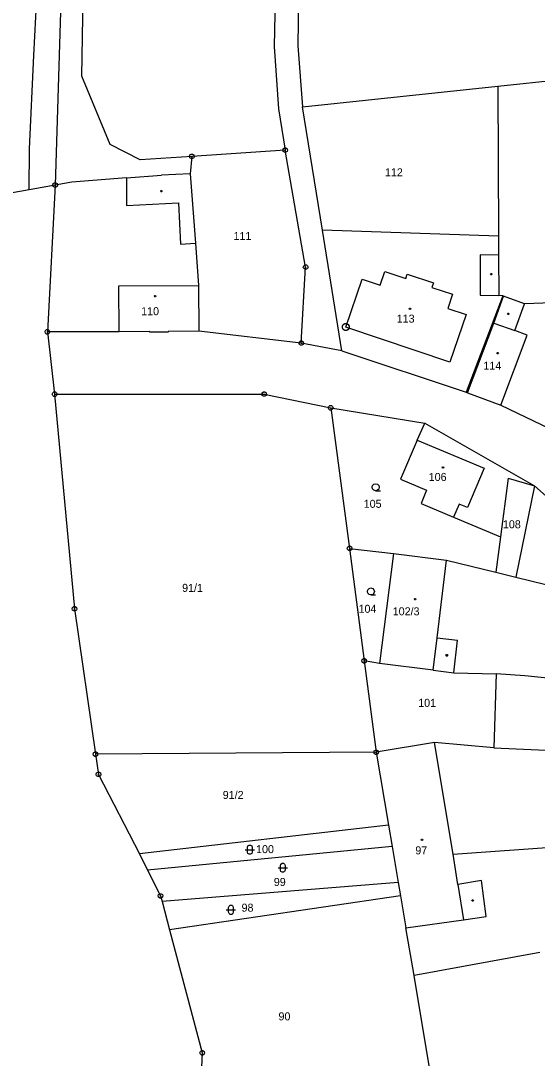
# Model space of a CAD drawing. Extents: x -812394 to -807601, y -1013098 to -1009266.
# Drawn here: x -809886.4 to -809776.7, y -1010813 to -1010592.7 of the extents above; entities that cross this region are included whole.
import ezdxf

# ---------------------------------------------------------------- set-up
doc = ezdxf.new("R2010")
doc.units = 0
for name, color, linetype in [('KN_HRANICE', 7, 'Continuous'), ('KN_KULTURY', 7, 'Continuous'), ('KN_MEZNIKY', 7, 'Continuous'), ('KN_PARCELY', 7, 'Continuous'), ('KN_SLUCKY', 7, 'Continuous'), ('KN_VEDENI', 7, 'Continuous')]:
    doc.layers.add(name, color=color, linetype=linetype)

# ---------------------------------------------------------------- blocks, each defined once
blk = doc.blocks.new('101')
blk.add_line((-0.05, 0), (0.05, 0))
blk.add_lwpolyline([(0.19, 0.72), (0.53, 0.53), (0.72, 0.19), (0.72, -0.2), (0.53, -0.54), (0.19, -0.73), (-0.2, -0.73), (-0.54, -0.54), (-0.73, -0.2), (-0.73, 0.19), (-0.54, 0.53), (-0.2, 0.72), (0.19, 0.72)])
blk = doc.blocks.new('304')
blk.add_lwpolyline([(0, 0), (-0.38, 0.1), (-0.65, 0.37), (-0.75, 0.74), (-0.65, 1.11), (-0.38, 1.38), (-0.01, 1.48), (0.36, 1.38), (0.63, 1.11), (0.73, 0.73), (0.63, 0.35), (0.36, 0.08), (-0.02, -0.02), (0.98, -0.02)])
blk = doc.blocks.new('316')
for points in [[(-1, 1), (0.27, 1), (1, 1)], [(-0.5, 1.5), (-0.4, 1.79), (-0.15, 1.97), (0.16, 1.97), (0.41, 1.79), (0.51, 1.5), (0.51, 0.5), (0.41, 0.21), (0.16, 0.03), (-0.15, 0.03), (-0.4, 0.21), (-0.5, 0.5), (-0.5, 1.5)]]:
    blk.add_lwpolyline(points)
blk = doc.blocks.new('402')
blk.add_lwpolyline([(0.09, 0.15), (0.18, 0), (0.09, -0.15), (-0.09, -0.15), (-0.18, 0), (-0.09, 0.15), (0.09, 0.15)])
blk = doc.blocks.new('105')
blk.add_line((-0.12, 0), (0.12, 0))
blk.add_lwpolyline([(0.15, 0.48), (0.4, 0.3), (0.5, 0.01), (0.4, -0.28), (0.15, -0.46), (-0.16, -0.46), (-0.41, -0.28), (-0.51, 0.01), (-0.41, 0.3), (-0.16, 0.48), (0.15, 0.48)])

msp = doc.modelspace()

# ---------------------------------------------------------------- linework, layer by layer
at = {"layer": 'KN_HRANICE'}
for p, q in [((-809873.36, -1010604.47), (-809872.78, -1010570.15)), ((-809832.23, -1010581.05), (-809832.51, -1010598.19)), ((-809827.23, -1010580.92), (-809827.51, -1010598.06)), ((-809877.92, -1010590.8), (-809879.03, -1010627.62)), ((-809832.51, -1010598.19), (-809831.62, -1010611.42)), ((-809827.51, -1010598.06), (-809826.5, -1010610.99)), ((-809785.03, -1010606.6), (-809746.74, -1010602.54)), ((-809867.35, -1010619), (-809873.36, -1010604.47)), ((-809826.5, -1010610.99), (-809785.03, -1010606.6)), ((-809785.03, -1010606.6), (-809784.91, -1010638.49)), ((-809831.62, -1010611.42), (-809830.2, -1010620.19)), ((-809822.29, -1010637.21), (-809826.5, -1010610.99)), ((-809860.96, -1010622.27), (-809867.35, -1010619)), ((-809830.2, -1010620.19), (-809850.01, -1010621.53)), ((-809825.85, -1010645.04), (-809830.2, -1010620.19)), ((-809850.01, -1010621.53), (-809860.96, -1010622.27)), ((-809850.01, -1010621.53), (-809850.38, -1010625.24)), ((-809850.38, -1010625.24), (-809856.43, -1010625.49)), ((-809850.38, -1010625.24), (-809849.27, -1010639.96)), ((-809879.03, -1010627.62), (-809884.55, -1010628.63)), ((-809879.03, -1010627.62), (-809880.69, -1010658.8)), ((-809875.47, -1010626.99), (-809879.03, -1010627.62)), ((-809863.92, -1010626.08), (-809875.47, -1010626.99)), ((-809863.92, -1010626.08), (-809856.43, -1010625.49)), ((-809884.55, -1010628.63), (-809898.33, -1010631.14)), ((-809784.91, -1010638.49), (-809822.29, -1010637.21)), ((-809818.18, -1010662.82), (-809822.29, -1010637.21)), ((-809784.91, -1010638.49), (-809784.89, -1010642.49)), ((-809849.27, -1010639.96), (-809848.59, -1010648.97)), ((-809784.89, -1010642.49), (-809784.86, -1010651.09)), ((-809826.78, -1010661.18), (-809825.85, -1010645.04)), ((-809848.59, -1010648.97), (-809848.53, -1010658.67)), ((-809784.01, -1010651.14), (-809791.73, -1010671.61)), ((-809784.01, -1010651.14), (-809784.86, -1010651.09)), ((-809783.82, -1010651.21), (-809784.01, -1010651.14)), ((-809779.36, -1010652.87), (-809783.82, -1010651.21)), ((-809773.49, -1010652.65), (-809779.36, -1010652.87)), ((-809865.45, -1010658.79), (-809880.69, -1010658.8)), ((-809880.69, -1010658.8), (-809879.15, -1010672.04)), ((-809858.96, -1010658.74), (-809865.45, -1010658.79)), ((-809858.96, -1010658.89), (-809858.96, -1010658.74)), ((-809855.08, -1010658.87), (-809858.96, -1010658.89)), ((-809848.53, -1010658.67), (-809855.08, -1010658.72)), ((-809855.08, -1010658.72), (-809855.08, -1010658.87)), ((-809826.78, -1010661.18), (-809848.53, -1010658.67)), ((-809818.18, -1010662.82), (-809826.78, -1010661.18)), ((-809818.18, -1010662.82), (-809791.73, -1010671.61)), ((-809791.73, -1010671.61), (-809791.45, -1010671.71)), ((-809791.45, -1010671.71), (-809784.4, -1010674.33)), ((-809879.15, -1010672.04), (-809834.64, -1010672.02)), ((-809879.15, -1010672.04), (-809874.93, -1010717.6)), ((-809834.64, -1010672.02), (-809820.53, -1010674.93)), ((-809820.53, -1010674.93), (-809816.51, -1010704.77)), ((-809820.53, -1010674.93), (-809800.51, -1010678.2)), ((-809784.4, -1010674.33), (-809774.04, -1010679.33)), ((-809802.14, -1010681.76), (-809800.51, -1010678.2)), ((-809800.51, -1010678.2), (-809777.22, -1010691.48)), ((-809802.14, -1010681.76), (-809805.72, -1010690.09)), ((-809805.72, -1010690.09), (-809800.16, -1010692.42)), ((-809782.82, -1010689.83), (-809784.46, -1010702.29)), ((-809782.82, -1010689.83), (-809777.22, -1010691.48)), ((-809777.22, -1010691.48), (-809781.21, -1010710.87)), ((-809777.22, -1010691.48), (-809766.01, -1010701.62)), ((-809800.16, -1010692.42), (-809801.34, -1010695.22)), ((-809801.34, -1010695.22), (-809794.45, -1010698.17)), ((-809794.45, -1010698.17), (-809784.46, -1010702.29)), ((-809784.46, -1010702.29), (-809785.46, -1010709.82)), ((-809816.51, -1010704.77), (-809813.43, -1010728.67)), ((-809816.51, -1010704.77), (-809807.17, -1010705.86)), ((-809807.17, -1010705.86), (-809810.15, -1010729.19)), ((-809807.17, -1010705.86), (-809795.91, -1010707.24)), ((-809797.91, -1010723.76), (-809795.91, -1010707.24)), ((-809795.91, -1010707.24), (-809785.46, -1010709.82)), ((-809785.46, -1010709.82), (-809781.21, -1010710.87)), ((-809781.21, -1010710.87), (-809771.66, -1010713.22)), ((-809874.93, -1010717.6), (-809870.46, -1010748.48)), ((-809798.74, -1010730.64), (-809797.91, -1010723.76)), ((-809813.43, -1010728.67), (-809810.87, -1010748.08)), ((-809810.15, -1010729.19), (-809813.43, -1010728.67)), ((-809798.74, -1010730.64), (-809810.15, -1010729.19)), ((-809798.74, -1010730.64), (-809794.37, -1010731.2)), ((-809794.37, -1010731.2), (-809785.42, -1010731.43)), ((-809785.42, -1010731.43), (-809785.91, -1010747.13)), ((-809779.32, -1010731.85), (-809785.42, -1010731.43)), ((-809752.63, -1010734.46), (-809779.32, -1010731.85)), ((-809798.52, -1010745.99), (-809810.87, -1010748.08)), ((-809785.91, -1010747.13), (-809798.52, -1010745.99)), ((-809794.5, -1010769.7), (-809798.52, -1010745.99)), ((-809810.87, -1010748.08), (-809870.46, -1010748.48)), ((-809870.46, -1010748.48), (-809869.85, -1010752.77)), ((-809810.87, -1010748.08), (-809808.24, -1010763.58)), ((-809785.91, -1010747.13), (-809765.89, -1010748.07)), ((-809869.85, -1010752.77), (-809861.14, -1010769.64)), ((-809808.24, -1010763.58), (-809861.14, -1010769.64)), ((-809808.24, -1010763.58), (-809807.48, -1010768.06)), ((-809807.48, -1010768.06), (-809859.41, -1010773.1)), ((-809807.48, -1010768.06), (-809806.19, -1010775.7)), ((-809794.5, -1010769.7), (-809750.96, -1010766.66)), ((-809861.14, -1010769.64), (-809859.41, -1010773.1)), ((-809793.54, -1010776.17), (-809794.5, -1010769.7)), ((-809859.41, -1010773.1), (-809856.66, -1010778.59)), ((-809806.19, -1010775.7), (-809856.35, -1010779.75)), ((-809806.19, -1010775.7), (-809805.71, -1010778.53)), ((-809788.53, -1010775.31), (-809793.54, -1010776.17)), ((-809787.51, -1010782.96), (-809788.53, -1010775.31)), ((-809856.66, -1010778.59), (-809856.35, -1010779.75)), ((-809805.71, -1010778.53), (-809854.75, -1010785.76)), ((-809805.71, -1010778.53), (-809804.56, -1010785.33)), ((-809856.35, -1010779.75), (-809854.75, -1010785.76)), ((-809804.56, -1010785.33), (-809792.3, -1010783.63)), ((-809792.3, -1010783.63), (-809787.51, -1010782.96)), ((-809854.75, -1010785.76), (-809847.8, -1010811.91)), ((-809802.82, -1010795.47), (-809804.56, -1010785.33)), ((-809776.12, -1010790.59), (-809802.82, -1010795.47)), ((-809795, -1010842.25), (-809802.82, -1010795.47)), ((-809847.8, -1010811.91), (-809848.47, -1010824.63))]:
    msp.add_line(p, q, dxfattribs=at)
at = {"layer": 'KN_SLUCKY'}
for p, q in [((-809863.92, -1010626.08), (-809863.87, -1010631.99)), ((-809863.87, -1010631.99), (-809852.85, -1010631.39)), ((-809852.85, -1010631.39), (-809852.45, -1010640.17)), ((-809852.45, -1010640.17), (-809849.27, -1010639.96)), ((-809788.76, -1010642.46), (-809788.8, -1010650.98)), ((-809784.89, -1010642.49), (-809788.76, -1010642.46)), ((-809810.03, -1010648.9), (-809809.06, -1010645.99)), ((-809809.06, -1010645.99), (-809804.61, -1010647.48)), ((-809804.61, -1010647.48), (-809804.3, -1010646.54)), ((-809804.3, -1010646.54), (-809798.72, -1010648.4)), ((-809865.55, -1010649.04), (-809848.59, -1010648.97)), ((-809865.45, -1010658.79), (-809865.55, -1010649.04)), ((-809817.34, -1010657.79), (-809813.83, -1010647.63)), ((-809813.83, -1010647.63), (-809810.03, -1010648.9)), ((-809798.72, -1010648.4), (-809799.03, -1010649.34)), ((-809799.03, -1010649.34), (-809794.68, -1010650.8)), ((-809794.68, -1010650.8), (-809795.68, -1010653.8)), ((-809788.8, -1010650.98), (-809784.86, -1010651.09)), ((-809785.89, -1010656.93), (-809783.82, -1010651.21)), ((-809781.46, -1010658.5), (-809779.36, -1010652.87)), ((-809791.45, -1010671.71), (-809785.89, -1010656.93)), ((-809785.89, -1010656.93), (-809781.46, -1010658.5)), ((-809778.83, -1010659.48), (-809781.46, -1010658.5)), ((-809784.4, -1010674.33), (-809778.83, -1010659.48)), ((-809802.14, -1010681.76), (-809787.93, -1010687.73)), ((-809787.93, -1010687.73), (-809791.51, -1010696.11)), ((-809793.26, -1010695.37), (-809794.45, -1010698.17)), ((-809791.51, -1010696.11), (-809793.26, -1010695.37)), ((-809797.91, -1010723.76), (-809793.59, -1010724.28)), ((-809794.37, -1010731.2), (-809793.59, -1010724.28)), ((-809793.54, -1010776.17), (-809792.3, -1010783.63))]:
    msp.add_line(p, q, dxfattribs=at)
msp.add_lwpolyline([(-809795.68, -1010653.8), (-809791.74, -1010655.11), (-809795.22, -1010665.26), (-809817.34, -1010657.79)], dxfattribs=at)
at = {"layer": 'KN_VEDENI'}
for p, q in [((-809883.6, -1010600.07), (-809882.5, -1010579.93)), ((-809884.5, -1010619.95), (-809883.6, -1010600.07)), ((-809884.55, -1010628.63), (-809884.5, -1010619.95))]:
    msp.add_line(p, q, dxfattribs=at)

# ---------------------------------------------------------------- block references
at = {"layer": 'KN_KULTURY'}
for name, p in [('402', (-809856.47, -1010628.94)), ('402', (-809786.45, -1010646.52)), ('402', (-809857.81, -1010651.2)), ('402', (-809803.7, -1010653.89)), ('402', (-809782.84, -1010654.95)), ('402', (-809785.08, -1010663.3)), ('402', (-809796.68, -1010687.62)), ('304', (-809810.97, -1010692.52)), ('304', (-809811.97, -1010714.65)), ('402', (-809802.61, -1010715.55)), ('402', (-809795.87, -1010727.49)), ('316', (-809837.72, -1010769.76)), ('402', (-809801.13, -1010766.65)), ('316', (-809830.72, -1010773.59)), ('402', (-809790.39, -1010779.57)), ('316', (-809841.72, -1010782.52))]:
    msp.add_blockref(name, p, dxfattribs=at)
at = {"layer": 'KN_MEZNIKY'}
for name, p in [('105', (-809850.01, -1010621.53)), ('105', (-809830.2, -1010620.19)), ('105', (-809879.03, -1010627.62)), ('105', (-809825.85, -1010645.04)), ('105', (-809880.69, -1010658.8)), ('101', (-809817.32, -1010657.75)), ('105', (-809826.78, -1010661.18)), ('105', (-809879.15, -1010672.04)), ('105', (-809834.64, -1010672.02)), ('105', (-809820.53, -1010674.93)), ('105', (-809816.51, -1010704.77)), ('105', (-809874.93, -1010717.6)), ('105', (-809813.43, -1010728.67)), ('105', (-809870.46, -1010748.48)), ('105', (-809810.87, -1010748.08)), ('105', (-809869.85, -1010752.77)), ('105', (-809856.66, -1010778.59)), ('105', (-809847.8, -1010811.91))]:
    msp.add_blockref(name, p, dxfattribs=at)

# ---------------------------------------------------------------- texts
at = {"layer": 'KN_PARCELY'}
for s, p in [('112', (-809809.01, -1010625.77)), ('111', (-809841.17, -1010639.28)), ('110', (-809860.78, -1010655.25)), ('113', (-809806.51, -1010656.83)), ('114', (-809788.11, -1010666.82)), ('106', (-809799.72, -1010690.45)), ('105', (-809813.52, -1010696.15)), ('108', (-809783.96, -1010700.5)), ('91/1', (-809852.08, -1010714)), ('104', (-809814.62, -1010718.45)), ('102/3', (-809807.36, -1010718.99)), ('101', (-809801.95, -1010738.42)), ('91/2', (-809843.46, -1010757.98)), ('100', (-809836.38, -1010769.49)), ('97', (-809802.56, -1010769.74)), ('99', (-809832.61, -1010776.46)), ('98', (-809839.46, -1010781.92)), ('90', (-809831.62, -1010805))]:
    msp.add_text(s, height=1.7, dxfattribs=at).set_placement(p)

doc.saveas('drawing.dxf')
